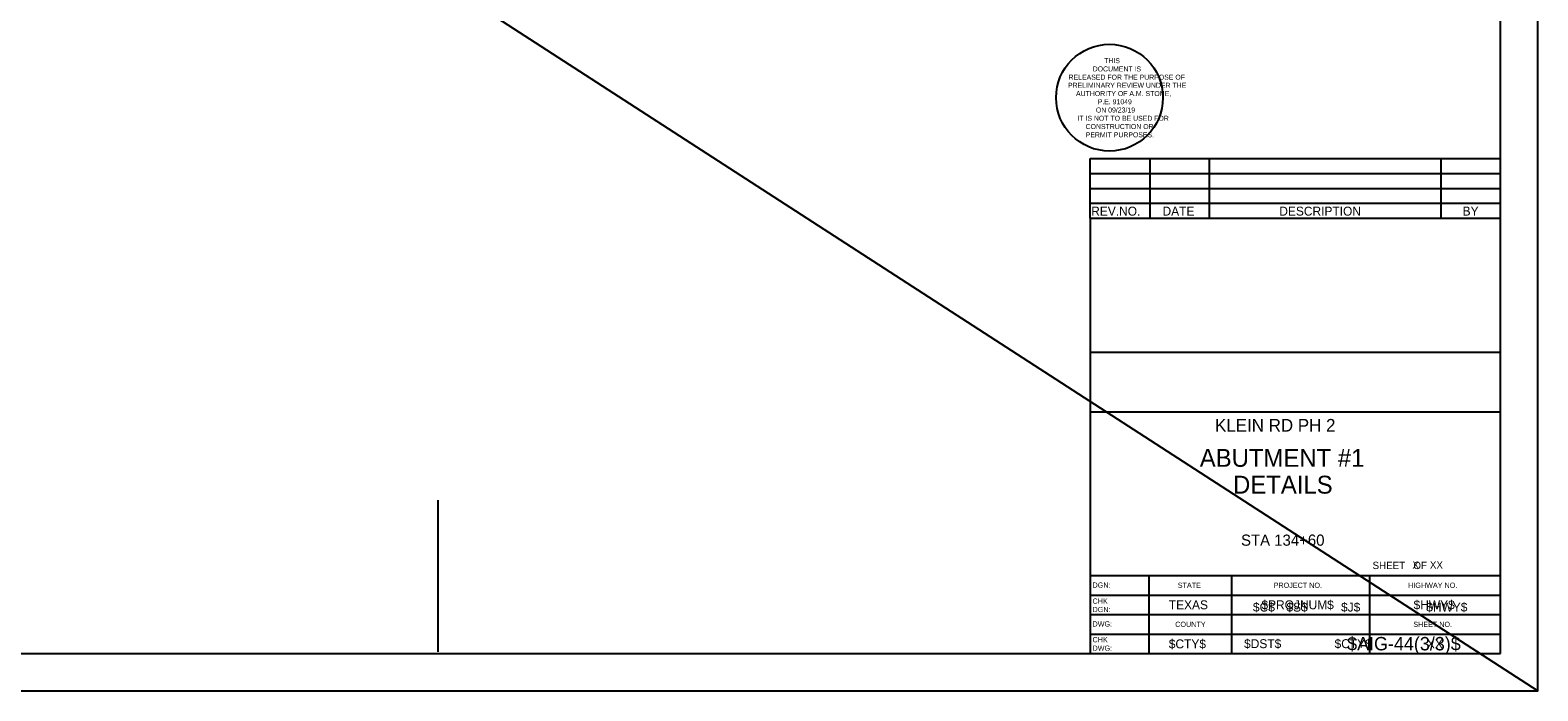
# Model space of a CAD drawing. Extents: x 970 to 1074, y 989 to 1045.
# Drawn here: x 1013.75 to 1034, y 1023 to 1031.88 of the extents above; entities that cross this region are included whole.
import ezdxf

# ---------------------------------------------------------------- set-up
doc = ezdxf.new("R2010")
doc.units = 0
for name, color, linetype in [('BORD_lines_major', 7, 'Continuous'), ('BORD_lines_minor', 7, 'Continuous'), ('BORD_text_large_1', 7, 'Continuous'), ('BORD_text_large_2', 7, 'Continuous'), ('BORD_text_SHEET', 7, 'Continuous'), ('BORD_text_small_1', 7, 'Continuous'), ('BORD_text_small_3', 7, 'Continuous'), ('BORD_text_small_proj', 7, 'Continuous'), ('C-MS-ANNO-TTLB-STMP', 7, 'Continuous'), ('D_BATCH_PLOT', 7, 'Continuous'), ('D_SHEET', 7, 'Continuous'), ('D_SHEET_NUM_CODE', 7, 'Continuous'), ('D_SHEET_TXT_SUB_CODE', 7, 'Continuous'), ('Working Level 1', 7, 'Continuous')]:
    doc.layers.add(name, color=color, linetype=linetype)

msp = doc.modelspace()

# ---------------------------------------------------------------- linework, layer by layer
at = {"layer": 'BORD_lines_major'}
for p, q in [((1033.5, 1023.5), (1033.5, 1044.382)), ((1002.413, 1023.5), (1033.5, 1023.5))]:
    msp.add_line(p, q, dxfattribs=at)
at = {"layer": 'BORD_lines_minor'}
for p, q in [((1027.988, 1030.15), (1033.5, 1030.15)), ((1027.988, 1029.35), (1027.988, 1030.15)), ((1028.788, 1030.15), (1028.788, 1029.35)), ((1029.588, 1030.15), (1029.588, 1029.35)), ((1032.7, 1029.35), (1032.7, 1030.15)), ((1027.988, 1029.95), (1033.5, 1029.95)), ((1027.988, 1029.75), (1033.5, 1029.75)), ((1027.988, 1029.55), (1033.5, 1029.55)), ((1027.988, 1029.35), (1033.5, 1029.35)), ((1027.988, 1029.35), (1027.988, 1027.55)), ((1027.988, 1027.55), (1033.5, 1027.55)), ((1027.988, 1027.55), (1027.988, 1023.5)), ((1027.988, 1026.75), (1033.5, 1026.75)), ((1027.988, 1024.55), (1033.5, 1024.55)), ((1028.776, 1024.55), (1028.776, 1023.5)), ((1029.888, 1024.55), (1029.888, 1023.5)), ((1031.738, 1024.55), (1031.738, 1023.5)), ((1027.988, 1024.287), (1033.5, 1024.287)), ((1027.988, 1024.025), (1033.5, 1024.025)), ((1027.988, 1023.762), (1033.5, 1023.762))]:
    msp.add_line(p, q, dxfattribs=at)
at = {"layer": 'C-MS-ANNO-TTLB-STMP'}
msp.add_circle((1028.248, 1030.969), 0.717, dxfattribs=at)
at = {"layer": 'D_BATCH_PLOT'}
msp.add_lwpolyline([(1000, 1023), (1034, 1023), (1034, 1045), (1000, 1045)], close=True, dxfattribs=at)
at = {"layer": 'D_SHEET'}
for p, q in [((1034, 1023), (1034, 1045)), ((1000, 1023), (1034, 1023))]:
    msp.add_line(p, q, dxfattribs=at)
at = {"layer": 'Working Level 1'}
for p, q in [((1000, 1045), (1034, 1023)), ((1019.229, 1025.564), (1019.229, 1023.525))]:
    msp.add_line(p, q, dxfattribs=at)

# ---------------------------------------------------------------- texts
at = {"layer": 'BORD_lines_minor'}
for s, p in [('REV.NO.', (1028.002, 1029.385)), ('DATE', (1028.96, 1029.385)), ('DESCRIPTION', (1030.528, 1029.385)), ('BY', (1032.99, 1029.385))]:
    msp.add_text(s, height=0.12, rotation=359.9834, dxfattribs=at).set_placement(p)
msp.add_text('KLEIN RD PH 2', height=0.17, dxfattribs=at).set_placement((1029.665, 1026.483))
at = {"layer": 'BORD_text_large_1'}
for s, p in [('ABUTMENT #1', (1029.46, 1026.01)), ('DETAILS', (1029.907, 1025.65))]:
    msp.add_text(s, height=0.24, dxfattribs=at).set_placement(p)
at = {"layer": 'BORD_text_large_2'}
msp.add_text('STA 134+60', height=0.15, dxfattribs=at).set_placement((1030.014, 1024.95))
at = {"layer": 'BORD_text_SHEET'}
msp.add_text('XX', height=0.12, dxfattribs=at).set_placement((1032.51, 1023.571))
at = {"layer": 'BORD_text_small_1'}
msp.add_text('SHEET   OF', height=0.0984, dxfattribs=at).set_placement((1031.78, 1024.636))
at = {"layer": 'BORD_text_small_3'}
msp.add_text('X    XX', height=0.0984, dxfattribs=at).set_placement((1032.316, 1024.642))
at = {"layer": 'BORD_text_small_proj'}
for s, height, p in [('DGN:', 0.07, (1028.02, 1024.386)), ('STATE', 0.07, (1029.164, 1024.384)), ('PROJECT NO.', 0.07, (1030.452, 1024.384)), ('HIGHWAY NO.', 0.07, (1032.258, 1024.384)), ('CHK', 0.07, (1028.02, 1024.171)), ('DGN:', 0.07, (1028.02, 1024.058)), ('TEXAS', 0.12, (1029.044, 1024.096)), ('$HWY$', 0.12, (1032.331, 1024.096)), ('DWG:', 0.07, (1028.02, 1023.864)), ('COUNTY', 0.07, (1029.13, 1023.859)), ('SHEET NO.', 0.07, (1032.327, 1023.859)), ('CHK', 0.07, (1028.02, 1023.653)), ('$CTY$', 0.12, (1029.044, 1023.571)), ('DWG:', 0.07, (1028.02, 1023.539))]:
    msp.add_text(s, height=height, rotation=359.9834, dxfattribs=at).set_placement(p)
msp.add_text('$PROJNUM$', height=0.12, dxfattribs=at).set_placement((1030.288, 1024.096))
at = {"layer": 'C-MS-ANNO-TTLB-STMP'}
for s, height, p in [('DOCUMENT IS', 0.06723, (1028.022, 1031.322)), ('THIS', 0.0672, (1028.176, 1031.433)), ('PRELIMINARY REVIEW UNDER THE', 0.06723, (1027.69, 1031.102)), ('RELEASED FOR THE PURPOSE OF', 0.06723, (1027.698, 1031.211)), ('AUTHORITY OF A.M. STONE,', 0.06723, (1027.798, 1030.991)), ('ON 09/23/19', 0.06723, (1028.065, 1030.77)), ('P.E. 91049', 0.0672, (1028.089, 1030.881)), ('IT IS NOT TO BE USED FOR', 0.06723, (1027.817, 1030.659)), ('CONSTRUCTION OR', 0.06723, (1027.927, 1030.548)), ('PERMIT PURPOSES.', 0.06723, (1027.928, 1030.437))]:
    msp.add_text(s, height=height, rotation=360, dxfattribs=at).set_placement(p)
at = {"layer": 'D_SHEET_NUM_CODE'}
msp.add_text('$AIG-44(3/3)$', height=0.18, dxfattribs=at).set_placement((1031.439, 1023.544))
at = {"layer": 'D_SHEET_TXT_SUB_CODE'}
for s, p in [('$C$', (1030.174, 1024.065)), ('$S$', (1030.624, 1024.065)), ('$J$', (1031.357, 1024.065)), ('$HWY$', (1032.501, 1024.065)), ('$DST$', (1030.055, 1023.574)), ('$CTY$', (1031.27, 1023.574))]:
    msp.add_text(s, height=0.12, dxfattribs=at).set_placement(p)

doc.saveas('drawing.dxf')
